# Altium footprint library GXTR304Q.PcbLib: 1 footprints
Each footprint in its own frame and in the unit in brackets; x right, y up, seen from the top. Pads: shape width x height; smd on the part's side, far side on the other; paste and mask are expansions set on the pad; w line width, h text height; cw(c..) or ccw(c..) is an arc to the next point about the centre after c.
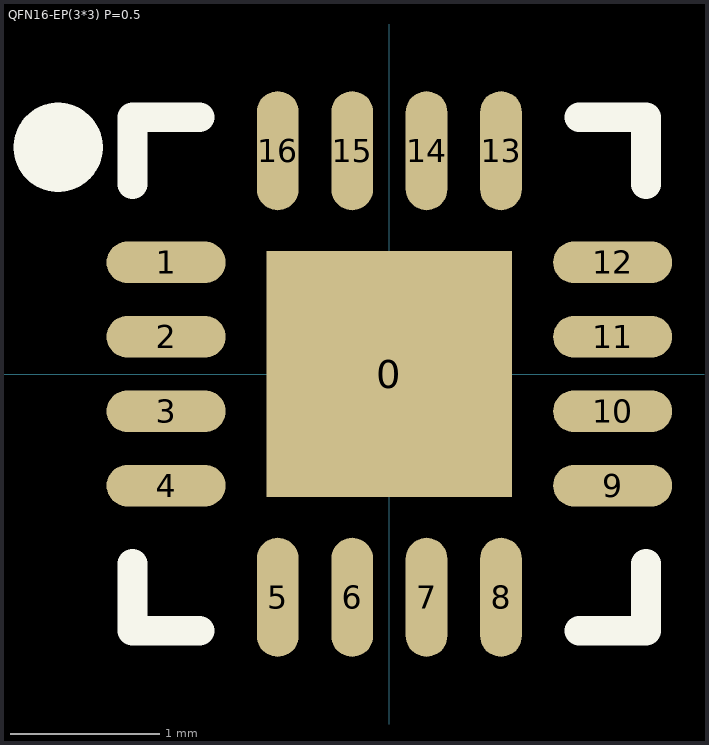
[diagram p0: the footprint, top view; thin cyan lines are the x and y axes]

## QFN16-EP(3*3) P=0.5 [mm]
pads (17):
  rect 1.65x1.65 smd paste+0 mask+0.051: 0(0,0)
  oval 0.8x0.28 smd paste+0 mask+0.051: 1(-1.5,0.75) 2(-1.5,0.25) 3(-1.5,-0.25) 4(-1.5,-0.75) 9(1.5,-0.75) 10(1.5,-0.25) 11(1.5,0.25) 12(1.5,0.75)
  oval 0.28x0.8 smd paste+0 mask+0.051: 5(-0.75,-1.5) 6(-0.25,-1.5) 7(0.25,-1.5) 8(0.75,-1.5) 13(0.75,1.5) 14(0.25,1.5) 15(-0.25,1.5) 16(-0.75,1.5)
Top Overlay:
  lines w0.2: -1.725,-1.275 -1.725,-1.725 -1.275,-1.725 ; -1.725,1.275 -1.725,1.725 -1.275,1.725 ; 1.275,-1.725 1.725,-1.725 1.725,-1.275 ; 1.275,1.725 1.725,1.725 1.725,1.275
  lines w0.3: -2.075,1.521 cw(c-2.225,1.523) -2.075,1.524
3D body "QFN-16-3.00X3.00-P0.5.STEP": height 0.81, standoff 0, extent -1.521,-1.521 1.499,1.499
